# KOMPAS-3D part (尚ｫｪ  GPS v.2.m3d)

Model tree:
1. Эскиз:1
2. Операция выдавливания:1
     Расстояние 1 = 2
3. Эскиз:3
4. Вырезать элемент выдавливания:4  (labels: Текстолит ГОСТ 5-78; SYSTEM_PROPERTY_ADDITIONAL_FOR:9.000000)
     Расстояние 1 = 2

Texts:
  Текстолит ГОСТ 5-78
